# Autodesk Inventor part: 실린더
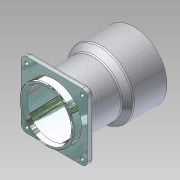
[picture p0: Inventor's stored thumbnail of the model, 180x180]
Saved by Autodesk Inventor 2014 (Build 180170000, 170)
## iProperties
Manager: KYOUNG IL JANG
Company: 한국ATC센터
Created: 2012-10
Part Number: 실린더
Material: 일반
Document SubType Name: 모델링
Density: 1 g/cm^3
Checked By: KYOUNG IL JANG
Vendor: CBT Solutions
Designer: KYOUNG IL JANG
Appearance: _시험_알루미늄 표면거칠기
Author: KYOUNG IL JANG
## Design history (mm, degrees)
sketch "스케치1"
  geometry: L1 (0, 0)-(0, 112); L2 (30, 0)-(30, 112); L3 (30, 112)-(42.5, 112); L4 (42.5, 112)-(42.5, 69); L5 (42.5, 69)-(35, 61); L6 (35, 61)-(35, 0); L7 (35, 0)-(30, 0)
  constraints: 14 end point, 4 parallel, 2 point on line, 1 perpendicular, 1 vertical
  dimensions: "d0" = 112 distance of L1.start L1.end; "d2" = 85 diameter of L4 L1; "d3" = 70 diameter of L6 L1; "d5" = 60 diameter of L2 L1; "d33" = 43 distance of L3.end L4.end; "d34" = 51 distance from line of L3 L5.end
revolve "회전1" stored, may be unused: angle "d6" = 90 deg
node "작업 평면1"
sketch "스케치2"
  geometry: L1 (-42.5, 42.5)-(42.5, 42.5); L2 (42.5, 42.5)-(42.5, -42.5); L3 (42.5, -42.5)-(-42.5, -42.5); L4 (-42.5, -42.5)-(-42.5, 42.5); C1 r 35 at (0, 0) reference; 3 further points
  constraints: 8 end point, 2 midpoint, 2 parallel, 2 perpendicular, 1 horizontal, 1 horizontal alignment, 1 vertical alignment
  dimensions: "d8" = 85 distance of L1.end L2.end
extrude "돌출1" join sketch "스케치2" distance "d9" = 8; taper "d10" = 0 deg
fillet "모깎기1" dims "d11" = 7, "d12" = 3
sketch "스케치3"
  geometry: L1 (0, 42.5)-(0, 30); 4 further points
  constraints: 2 end point, 2 vertical alignment, 1 midpoint, 1 point on line, 1 vertical, 2 other
hole "구멍1" sketch "스케치3" at (0, 36.25) diameter "d14" = 4.134; stored, may be unused: countersink angle "d18" = 90 deg, drill point angle "d20" = 118 deg; dims "d15" = 12, "d16" = 4, "d17" = 2, "d19" = 15
sketch "스케치4"
  geometry: C1 r 1.621 at (35.5, -35.5) reference; C2 r 1.621 at (35.5, 35.5) reference; C3 r 1.621 at (-35.5, -35.5) reference; C4 r 1.621 at (-35.5, 35.5) reference; 1 further point
hole "구멍2" sketch "스케치4" at (35.5, 35.5), (35.5, -35.5), (-35.5, -35.5), (-35.5, 35.5) diameter "d26" = 4.5; stored, may be unused: countersink angle "d30" = 90 deg, drill point angle "d32" = 118 deg; dims "d27" = 12, "d28" = 8, "d29" = 4.4, "d31" = 15
chamfer "모따기1" distance "d35" = 5; stored, may be unused: second distance "d36" = 2, angle "d37" = 20 deg
chamfer "모따기2" distance "d38" = 1; stored, may be unused: second distance "d39" = 2, angle "d40" = 20 deg
node "솔리드1"
pattern_circular "원형 패턴1" dims angle "d22" = 360 deg
node "참조1"
node "참조2"
node "참조3"
node "참조4"
other parameters: "KFactor" = 4.4
